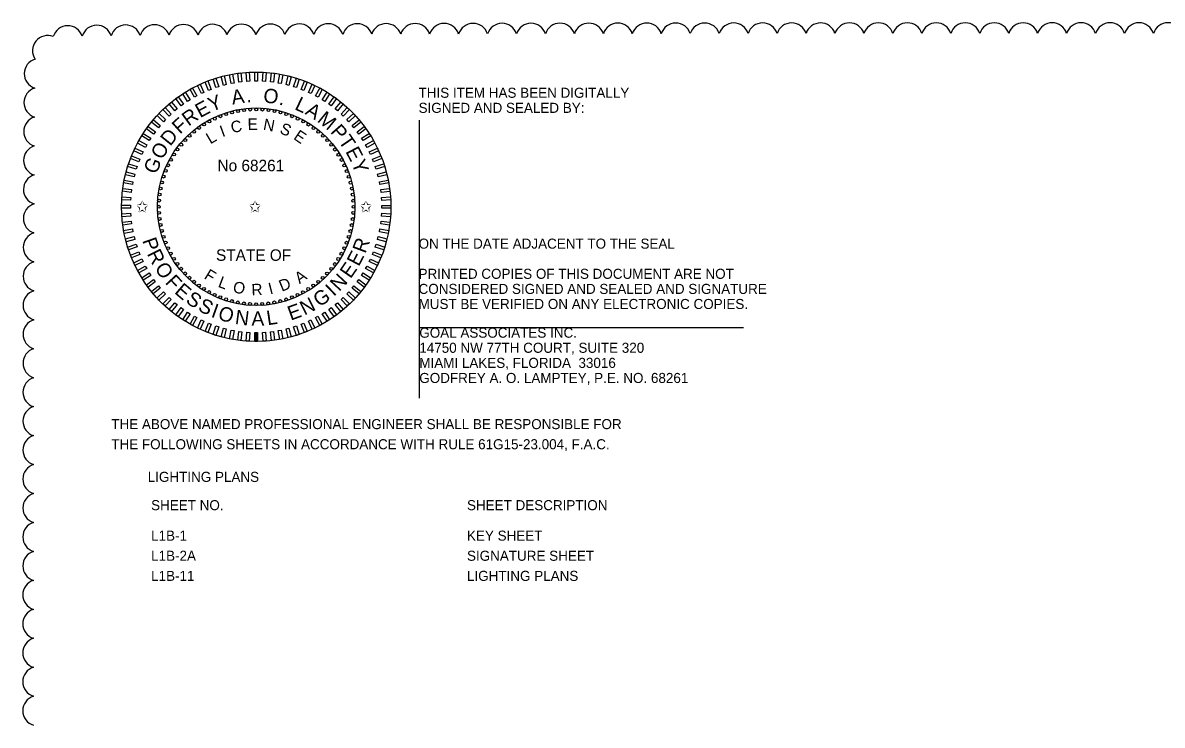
# Model space of a CAD drawing. Extents: x -811.2 to -767.6, y -2295.2 to -2235.1.
# Drawn here: x -811.11 to -803.18, y -2252.32 to -2247.44 of the extents above; entities that cross this region are included whole.
import ezdxf

# ---------------------------------------------------------------- set-up
doc = ezdxf.new("R2010")
doc.units = 0
for name, color, linetype in [('AdhocPoint_dp', 7, 'Continuous'), ('Cloud_dp', 7, 'Continuous'), ('PlotBorder_dp', 7, 'Continuous'), ('TextMinor', 7, 'Continuous'), ('TextMisc', 7, 'Continuous'), ('TextShtNo', 7, 'Continuous')]:
    doc.layers.add(name, color=color, linetype=linetype)

msp = doc.modelspace()

# ---------------------------------------------------------------- linework, layer by layer
at = {"layer": 'AdhocPoint_dp'}
for p, q in [((-808.3546, -2248.1122), (-808.3546, -2250.0469)), ((-808.3546, -2249.5569), (-806.0979, -2249.5569))]:
    msp.add_line(p, q, dxfattribs=at)
at = {"layer": 'Cloud_dp'}
for centre, start, end in [((-810.8012, -2247.5613), 18.59454, 163.59454), ((-810.5999, -2247.5581), 18.21421, 163.21421), ((-810.3985, -2247.5559), 18.04696, 163.04696), ((-810.197, -2247.5542), 17.94666, 162.94666), ((-809.9955, -2247.5527), 17.87787, 162.87787), ((-809.794, -2247.5515), 17.82689, 162.82689), ((-809.5924, -2247.5504), 17.78716, 162.78716), ((-809.3909, -2247.5495), 17.75505, 162.75505), ((-809.1894, -2247.5486), 17.72841, 162.72841), ((-808.9878, -2247.5478), 17.70584, 162.70584), ((-808.7863, -2247.5471), 17.6864, 162.6864), ((-808.5848, -2247.5465), 17.66942, 162.66942), ((-808.3832, -2247.546), 17.65443, 162.65443), ((-808.1817, -2247.5454), 17.64106, 162.64106), ((-807.9801, -2247.545), 17.62905, 162.62905), ((-807.7786, -2247.5445), 17.61817, 162.61817), ((-807.577, -2247.5441), 17.60826, 162.60826), ((-807.3755, -2247.5438), 17.59919, 162.59919), ((-807.174, -2247.5434), 17.59084, 162.59084), ((-806.9724, -2247.5431), 17.58312, 162.58312), ((-806.7709, -2247.5428), 17.57595, 162.57595), ((-806.5693, -2247.5426), 17.56928, 162.56928), ((-806.3678, -2247.5424), 17.56305, 162.56305), ((-806.1662, -2247.5421), 17.55721, 162.55721), ((-805.9647, -2247.5419), 17.55172, 162.55172), ((-805.7631, -2247.5418), 17.54655, 162.54655), ((-805.5616, -2247.5416), 17.54167, 162.54167), ((-805.3601, -2247.5415), 17.53705, 162.53705), ((-805.1585, -2247.5414), 17.53267, 162.53267), ((-804.957, -2247.5413), 17.52851, 162.52851), ((-804.7554, -2247.5412), 17.52455, 162.52455), ((-804.5539, -2247.5411), 17.52079, 162.52079), ((-804.3523, -2247.541), 17.51719, 162.51719), ((-804.1508, -2247.541), 17.51375, 162.51375), ((-803.9492, -2247.5409), 17.51046, 162.51046), ((-803.7477, -2247.5409), 17.50731, 162.50731), ((-803.5461, -2247.5409), 17.50428, 162.50428), ((-803.3446, -2247.5409), 17.50138, 162.50138), ((-803.143, -2247.5409), 17.5, 162.5), ((-810.9414, -2247.6297), 68.43954, 213.43954), ((-810.999, -2247.7891), 106.80445, 251.80445), ((-811.001, -2247.9905), 107.04367, 252.04367), ((-811.0025, -2248.192), 107.15618, 252.15618), ((-811.0035, -2248.3935), 107.22533, 252.22533), ((-811.0044, -2248.595), 107.27338, 252.27338), ((-811.0052, -2248.7966), 107.30928, 252.30928), ((-811.0058, -2248.9981), 107.33743, 252.33743), ((-811.0063, -2249.1996), 107.36027, 252.36027), ((-811.0068, -2249.4012), 107.37928, 252.37928), ((-811.0072, -2249.6027), 107.39543, 252.39543), ((-811.0075, -2249.8042), 107.40937, 252.40937), ((-811.0078, -2250.0058), 107.42156, 252.42156), ((-811.0081, -2250.2073), 107.43234, 252.43234), ((-811.0083, -2250.4089), 107.44197, 252.44197), ((-811.0085, -2250.6104), 107.45063, 252.45063), ((-811.0086, -2250.812), 107.45847, 252.45847), ((-811.0088, -2251.0135), 107.46563, 252.46563), ((-811.0089, -2251.2151), 107.47218, 252.47218), ((-811.009, -2251.4166), 107.47822, 252.47822), ((-811.009, -2251.6181), 107.4838, 252.4838), ((-811.0091, -2251.8197), 107.48899, 252.48899), ((-811.0091, -2252.0212), 107.49382, 252.49382), ((-811.0091, -2252.2228), 107.49843, 252.49843)]:
    msp.add_arc(centre, 0.1057, start, end, dxfattribs=at)
at = {"layer": 'TextMinor'}
for radius in [0.9375, 0.6875]:
    msp.add_circle((-809.4901, -2248.7156), radius, dxfattribs=at)
at = {"layer": 'TextShtNo'}
for p, q in [((-809.5001, -2249.6532), (-809.5003, -2249.5907)), ((-809.4901, -2249.6531), (-809.4903, -2249.5906)), ((-809.4801, -2249.6531), (-809.4803, -2249.5906))]:
    msp.add_line(p, q, dxfattribs=at)
for points in [[(-809.5897, -2247.8462), (-809.6097, -2247.8488), (-809.6175, -2247.7868), (-809.5975, -2247.7843)], [(-809.5349, -2247.8417), (-809.555, -2247.843), (-809.559, -2247.7806), (-809.5388, -2247.7794)], [(-809.4799, -2247.8406), (-809.5001, -2247.8406), (-809.5001, -2247.7782), (-809.4799, -2247.7782)], [(-809.425, -2247.843), (-809.4452, -2247.8417), (-809.4412, -2247.7794), (-809.4211, -2247.7807)], [(-809.3703, -2247.8488), (-809.3904, -2247.8463), (-809.3825, -2247.7843), (-809.3625, -2247.7868)], [(-809.8535, -2247.9195), (-809.8717, -2247.9281), (-809.8983, -2247.8716), (-809.8801, -2247.863)], [(-809.8028, -2247.8983), (-809.8215, -2247.9057), (-809.8445, -2247.8477), (-809.8258, -2247.8402)], [(-809.7508, -2247.8803), (-809.77, -2247.8865), (-809.7893, -2247.8271), (-809.7701, -2247.8209)], [(-809.6979, -2247.8656), (-809.7174, -2247.8706), (-809.7329, -2247.8101), (-809.7134, -2247.8051)], [(-809.6441, -2247.8542), (-809.6639, -2247.858), (-809.6756, -2247.7966), (-809.6558, -2247.7929)], [(-809.3162, -2247.858), (-809.336, -2247.8542), (-809.3243, -2247.7929), (-809.3045, -2247.7967)], [(-809.2626, -2247.8706), (-809.2822, -2247.8656), (-809.2667, -2247.8051), (-809.2471, -2247.8102)], [(-809.21, -2247.8866), (-809.2292, -2247.8803), (-809.2099, -2247.821), (-809.1907, -2247.8272)], [(-809.1585, -2247.9058), (-809.1773, -2247.8984), (-809.1543, -2247.8403), (-809.1355, -2247.8477)], [(-809.1083, -2247.9282), (-809.1266, -2247.9196), (-809.1, -2247.8631), (-809.0817, -2247.8717)], [(-809.9504, -2247.9714), (-809.9674, -2247.9822), (-810.0009, -2247.9295), (-809.9838, -2247.9186)], [(-809.9027, -2247.9439), (-809.9204, -2247.9537), (-809.9505, -2247.8989), (-809.9328, -2247.8892)], [(-809.0596, -2247.9537), (-809.0773, -2247.944), (-809.0473, -2247.8893), (-809.0296, -2247.899)], [(-809.0127, -2247.9823), (-809.0297, -2247.9715), (-808.9962, -2247.9187), (-808.9792, -2247.9296)], [(-810.0817, -2248.0708), (-810.0964, -2248.0846), (-810.1392, -2248.0391), (-810.1244, -2248.0253)], [(-810.04, -2248.0349), (-810.0556, -2248.0478), (-810.0954, -2247.9997), (-810.0798, -2247.9868)], [(-809.9962, -2248.0017), (-810.0125, -2248.0136), (-810.0492, -2247.9631), (-810.0329, -2247.9512)], [(-808.9676, -2248.0137), (-808.9839, -2248.0018), (-808.9472, -2247.9513), (-808.9308, -2247.9632)], [(-808.9245, -2248.0479), (-808.9401, -2248.035), (-808.9003, -2247.9869), (-808.8847, -2247.9998)], [(-808.8837, -2248.0847), (-808.8984, -2248.0709), (-808.8557, -2248.0254), (-808.841, -2248.0392)], [(-810.121, -2248.1092), (-810.1348, -2248.1239), (-810.1804, -2248.0812), (-810.1665, -2248.0665)], [(-808.8453, -2248.1241), (-808.8591, -2248.1093), (-808.8136, -2248.0666), (-808.7998, -2248.0813)], [(-810.192, -2248.1931), (-810.2039, -2248.2094), (-810.2544, -2248.1727), (-810.2426, -2248.1564)], [(-810.1579, -2248.15), (-810.1707, -2248.1656), (-810.2188, -2248.1258), (-810.206, -2248.1102)], [(-808.8094, -2248.1657), (-808.8223, -2248.1502), (-808.7742, -2248.1104), (-808.7613, -2248.1259)], [(-808.7762, -2248.2095), (-808.7881, -2248.1932), (-808.7376, -2248.1565), (-808.7257, -2248.1728)], [(-810.252, -2248.2852), (-810.2617, -2248.3028), (-810.3164, -2248.2728), (-810.3067, -2248.2551)], [(-810.2235, -2248.2382), (-810.2343, -2248.2552), (-810.287, -2248.2218), (-810.2762, -2248.2047)], [(-808.7459, -2248.2554), (-808.7567, -2248.2383), (-808.7039, -2248.2049), (-808.6931, -2248.2219)], [(-808.7184, -2248.303), (-808.7281, -2248.2853), (-808.6734, -2248.2552), (-808.6637, -2248.2729)], [(-810.2775, -2248.3338), (-810.2861, -2248.3521), (-810.3426, -2248.3255), (-810.334, -2248.3073)], [(-808.694, -2248.3523), (-808.7026, -2248.334), (-808.6461, -2248.3074), (-808.6375, -2248.3257)], [(-810.3192, -2248.4355), (-810.3254, -2248.4547), (-810.3848, -2248.4355), (-810.3786, -2248.4163)], [(-810.3, -2248.384), (-810.3074, -2248.4028), (-810.3654, -2248.3798), (-810.358, -2248.3611)], [(-808.6728, -2248.403), (-808.6802, -2248.3842), (-808.6222, -2248.3612), (-808.6147, -2248.38)], [(-808.6548, -2248.4549), (-808.661, -2248.4357), (-808.6016, -2248.4164), (-808.5954, -2248.4356)], [(-810.3351, -2248.4882), (-810.3401, -2248.5077), (-810.4006, -2248.4922), (-810.3956, -2248.4726)], [(-808.64, -2248.5079), (-808.6451, -2248.4883), (-808.5846, -2248.4728), (-808.5796, -2248.4924)], [(-810.3477, -2248.5417), (-810.3515, -2248.5615), (-810.4129, -2248.5498), (-810.4091, -2248.53)], [(-808.6287, -2248.5617), (-808.6325, -2248.5418), (-808.5711, -2248.5301), (-808.5673, -2248.55)], [(-810.3628, -2248.6505), (-810.3641, -2248.6707), (-810.4264, -2248.6668), (-810.4251, -2248.6466)], [(-810.357, -2248.5959), (-810.3595, -2248.6159), (-810.4215, -2248.6081), (-810.4189, -2248.588)], [(-808.6207, -2248.6161), (-808.6232, -2248.596), (-808.5613, -2248.5882), (-808.5588, -2248.6082)], [(-808.6162, -2248.6709), (-808.6174, -2248.6507), (-808.5551, -2248.6468), (-808.5539, -2248.6669)], [(-810.3652, -2248.7054), (-810.3652, -2248.7256), (-810.4276, -2248.7256), (-810.4276, -2248.7054)], [(-808.6151, -2248.7258), (-808.6151, -2248.7056), (-808.5527, -2248.7056), (-808.5527, -2248.7258)], [(-810.3641, -2248.7604), (-810.3628, -2248.7806), (-810.4251, -2248.7845), (-810.4264, -2248.7643)], [(-810.3595, -2248.8152), (-810.357, -2248.8352), (-810.4189, -2248.8431), (-810.4215, -2248.823)], [(-808.6233, -2248.8354), (-808.6207, -2248.8154), (-808.5588, -2248.8232), (-808.5613, -2248.8432)], [(-808.6175, -2248.7807), (-808.6162, -2248.7606), (-808.5539, -2248.7645), (-808.5551, -2248.7847)], [(-810.3516, -2248.8696), (-810.3478, -2248.8894), (-810.4091, -2248.9011), (-810.4129, -2248.8813)], [(-808.6325, -2248.8896), (-808.6287, -2248.8698), (-808.5674, -2248.8815), (-808.5712, -2248.9013)], [(-810.3402, -2248.9234), (-810.3352, -2248.9429), (-810.3957, -2248.9585), (-810.4007, -2248.9389)], [(-810.3255, -2248.9763), (-810.3192, -2248.9955), (-810.3786, -2249.0148), (-810.3849, -2248.9956)], [(-808.6611, -2248.9957), (-808.6548, -2248.9765), (-808.5954, -2248.9958), (-808.6017, -2249.015)], [(-808.6451, -2248.9431), (-808.6401, -2248.9236), (-808.5796, -2248.9391), (-808.5846, -2248.9586)], [(-810.3075, -2249.0283), (-810.3, -2249.0471), (-810.3581, -2249.07), (-810.3655, -2249.0513)], [(-808.6803, -2249.0472), (-808.6729, -2249.0285), (-808.6148, -2249.0514), (-808.6222, -2249.0702)], [(-810.2862, -2249.079), (-810.2776, -2249.0973), (-810.3341, -2249.1238), (-810.3427, -2249.1056)], [(-810.2618, -2249.1283), (-810.2521, -2249.1459), (-810.3068, -2249.176), (-810.3165, -2249.1583)], [(-808.7282, -2249.1461), (-808.7185, -2249.1284), (-808.6638, -2249.1585), (-808.6735, -2249.1762)], [(-808.7027, -2249.0974), (-808.6941, -2249.0792), (-808.6376, -2249.1057), (-808.6462, -2249.124)], [(-810.2344, -2249.1759), (-810.2236, -2249.1929), (-810.2763, -2249.2264), (-810.2871, -2249.2094)], [(-808.7568, -2249.1931), (-808.746, -2249.1761), (-808.6932, -2249.2095), (-808.704, -2249.2266)], [(-810.204, -2249.2217), (-810.1922, -2249.2381), (-810.2427, -2249.2748), (-810.2545, -2249.2584)], [(-810.1708, -2249.2656), (-810.158, -2249.2811), (-810.2061, -2249.3209), (-810.2189, -2249.3054)], [(-808.8224, -2249.2812), (-808.8095, -2249.2657), (-808.7614, -2249.3055), (-808.7743, -2249.321)], [(-808.7882, -2249.2382), (-808.7763, -2249.2219), (-808.7258, -2249.2586), (-808.7377, -2249.2749)], [(-810.135, -2249.3072), (-810.1211, -2249.3219), (-810.1667, -2249.3647), (-810.1805, -2249.35)], [(-810.0965, -2249.3465), (-810.0818, -2249.3603), (-810.1246, -2249.4059), (-810.1393, -2249.392)], [(-808.8985, -2249.3605), (-808.8838, -2249.3467), (-808.8411, -2249.3922), (-808.8558, -2249.406)], [(-808.8592, -2249.3221), (-808.8454, -2249.3073), (-808.7999, -2249.3501), (-808.8137, -2249.3648)], [(-810.0557, -2249.3834), (-810.0402, -2249.3962), (-810.08, -2249.4443), (-810.0955, -2249.4315)], [(-810.0127, -2249.4176), (-809.9964, -2249.4294), (-810.0331, -2249.4799), (-810.0494, -2249.4681)], [(-809.9676, -2249.449), (-809.9505, -2249.4598), (-809.984, -2249.5125), (-810.001, -2249.5017)], [(-809.0299, -2249.4599), (-809.0128, -2249.4491), (-808.9794, -2249.5018), (-808.9964, -2249.5126)], [(-808.984, -2249.4295), (-808.9677, -2249.4177), (-808.931, -2249.4682), (-808.9473, -2249.4801)], [(-808.9402, -2249.3964), (-808.9247, -2249.3835), (-808.8848, -2249.4316), (-808.9004, -2249.4445)], [(-809.9206, -2249.4775), (-809.9029, -2249.4872), (-809.933, -2249.542), (-809.9507, -2249.5322)], [(-809.8719, -2249.503), (-809.8536, -2249.5116), (-809.8802, -2249.5681), (-809.8985, -2249.5595)], [(-809.8217, -2249.5255), (-809.8029, -2249.5329), (-809.8259, -2249.591), (-809.8447, -2249.5835)], [(-809.1775, -2249.533), (-809.1587, -2249.5255), (-809.1357, -2249.5836), (-809.1545, -2249.591)], [(-809.1268, -2249.5117), (-809.1085, -2249.5031), (-809.0819, -2249.5596), (-809.1002, -2249.5682)], [(-809.0775, -2249.4873), (-809.0598, -2249.4776), (-809.0297, -2249.5323), (-809.0474, -2249.5421)], [(-809.7702, -2249.5447), (-809.751, -2249.5509), (-809.7703, -2249.6103), (-809.7895, -2249.6041)], [(-809.7176, -2249.5606), (-809.698, -2249.5657), (-809.7136, -2249.6261), (-809.7331, -2249.6211)], [(-809.6641, -2249.5733), (-809.6443, -2249.577), (-809.656, -2249.6384), (-809.6758, -2249.6346)], [(-809.6099, -2249.5825), (-809.5899, -2249.585), (-809.5977, -2249.647), (-809.6177, -2249.6444)], [(-809.5552, -2249.5883), (-809.5351, -2249.5896), (-809.539, -2249.6519), (-809.5592, -2249.6506)], [(-809.5003, -2249.5907), (-809.4801, -2249.5907), (-809.4801, -2249.6531), (-809.5003, -2249.6531)], [(-809.4453, -2249.5896), (-809.4252, -2249.5883), (-809.4213, -2249.6506), (-809.4414, -2249.6519)], [(-809.3906, -2249.585), (-809.3705, -2249.5825), (-809.3627, -2249.6445), (-809.3827, -2249.647)], [(-809.3362, -2249.5771), (-809.3163, -2249.5733), (-809.3046, -2249.6346), (-809.3245, -2249.6384)], [(-809.2824, -2249.5657), (-809.2628, -2249.5607), (-809.2473, -2249.6212), (-809.2668, -2249.6262)], [(-809.2294, -2249.551), (-809.2102, -2249.5447), (-809.1909, -2249.6041), (-809.2101, -2249.6104)]]:
    msp.add_lwpolyline(points, close=True, dxfattribs=at)
for centre in [(-809.7781, -2248.1024), (-809.739, -2248.0855), (-809.6989, -2248.0712), (-809.6581, -2248.0593), (-809.6165, -2248.0501), (-809.5745, -2248.0434), (-809.5321, -2248.0395), (-809.4896, -2248.0382), (-809.447, -2248.0395), (-809.4047, -2248.0436), (-809.3626, -2248.0503), (-809.3211, -2248.0596), (-809.2802, -2248.0715), (-809.2402, -2248.0859), (-809.2012, -2248.1029), (-809.9215, -2248.1933), (-809.8879, -2248.1672), (-809.8527, -2248.1433), (-809.816, -2248.1217), (-809.1633, -2248.1222), (-809.1266, -2248.1439), (-809.0915, -2248.1679), (-809.0579, -2248.194), (-809.9836, -2248.2515), (-809.9535, -2248.2214), (-809.026, -2248.2222), (-808.9959, -2248.2523), (-810.0618, -2248.3522), (-810.0379, -2248.317), (-810.0118, -2248.2834), (-808.9678, -2248.2842), (-808.9417, -2248.3179), (-808.9178, -2248.3531), (-810.1029, -2248.4267), (-810.0835, -2248.3888), (-808.8962, -2248.3898), (-808.8769, -2248.4277), (-810.1343, -2248.5057), (-810.1198, -2248.4657), (-808.86, -2248.4668), (-808.8456, -2248.5068), (-810.1555, -2248.5881), (-810.1462, -2248.5466), (-808.8338, -2248.5477), (-808.8245, -2248.5892), (-810.1622, -2248.6302), (-808.8179, -2248.6313), (-810.1676, -2248.7151), (-810.1662, -2248.6725), (-808.814, -2248.6737), (-808.8127, -2248.7162), (-810.1663, -2248.7576), (-810.1623, -2248.8), (-808.8181, -2248.8011), (-808.814, -2248.7587), (-810.1557, -2248.842), (-810.1464, -2248.8836), (-808.8341, -2248.8847), (-808.8248, -2248.8431), (-810.1346, -2248.9244), (-810.1202, -2248.9645), (-808.8604, -2248.9656), (-808.846, -2248.9255), (-810.1034, -2249.0036), (-810.0841, -2249.0415), (-808.8967, -2249.0425), (-808.8774, -2249.0046), (-810.0624, -2249.0782), (-810.0385, -2249.1134), (-808.9424, -2249.1143), (-808.9184, -2249.0791), (-810.0125, -2249.147), (-809.9844, -2249.179), (-809.9543, -2249.2091), (-809.0268, -2249.2099), (-808.9967, -2249.1798), (-808.9685, -2249.1479), (-809.9224, -2249.2373), (-809.8888, -2249.2634), (-809.8536, -2249.2873), (-809.1276, -2249.2879), (-809.0924, -2249.264), (-809.0587, -2249.238), (-809.817, -2249.309), (-809.7791, -2249.3284), (-809.74, -2249.3453), (-809.7, -2249.3598), (-809.6591, -2249.3717), (-809.6176, -2249.381), (-809.3637, -2249.3812), (-809.3222, -2249.372), (-809.2813, -2249.3601), (-809.2413, -2249.3457), (-809.2022, -2249.3289), (-809.1642, -2249.3096), (-809.5756, -2249.3877), (-809.5332, -2249.3917), (-809.4901, -2249.3931), (-809.4481, -2249.3918), (-809.4058, -2249.3878)]:
    msp.add_circle(centre, 0.01, dxfattribs=at)

# ---------------------------------------------------------------- texts
at = {"layer": 'PlotBorder_dp'}
for s, p in [('THIS ITEM HAS BEEN DIGITALLY', (-808.3596, -2247.9571)), ('SIGNED AND SEALED BY:', (-808.3596, -2248.0621)), ('ON THE DATE ADJACENT TO THE SEAL', (-808.3596, -2249.0071)), ('PRINTED COPIES OF THIS DOCUMENT ARE NOT ', (-808.3596, -2249.2171)), ('CONSIDERED SIGNED AND SEALED AND SIGNATURE ', (-808.3596, -2249.3221)), ('MUST BE VERIFIED ON ANY ELECTRONIC COPIES.', (-808.3596, -2249.4271)), ('GOAL ASSOCIATES INC.', (-808.3546, -2249.6269)), ('14750 NW 77TH COURT, SUITE 320', (-808.3546, -2249.7319)), ('MIAMI LAKES, FLORIDA  33016', (-808.3546, -2249.8369)), ('GODFREY A. O. LAMPTEY, P.E. NO. 68261', (-808.3546, -2249.9419)), ('THE ABOVE NAMED PROFESSIONAL ENGINEER SHALL BE RESPONSIBLE FOR ', (-810.4987, -2250.2631)), ('THE FOLLOWING SHEETS IN ACCORDANCE WITH RULE 61G15-23.004, F.A.C.', (-810.4987, -2250.4031)), ('LIGHTING PLANS', (-810.245, -2250.6301))]:
    msp.add_text(s, height=0.07, dxfattribs=at).set_placement(p)
at = {"layer": 'TextMisc'}
for s, p in [('SHEET NO.', (-810.2215, -2250.8271)), ('SHEET DESCRIPTION', (-808.0226, -2250.8271)), ('L1B-1', (-810.2215, -2251.0393)), ('KEY SHEET', (-808.0226, -2251.0393)), ('L1B-2A', (-810.2215, -2251.1793)), ('SIGNATURE SHEET', (-808.0226, -2251.1793)), ('L1B-11', (-810.2215, -2251.3193)), ('LIGHTING PLANS', (-808.0226, -2251.3193))]:
    msp.add_text(s, height=0.07, dxfattribs=at).set_placement(p)
at = {"layer": 'TextShtNo'}
for s, height, rotation, p in [('Y', 0.1, 21.06329, (-809.8021, -2248.0562)), ('A', 0.1, 8.80884, (-809.6551, -2248.005)), ('O', 0.1, 352.18771, (-809.4449, -2247.9875)), ('E', 0.1, 28.10553, (-809.8806, -2248.0994)), ('.', 0.1, 1.04184, (-809.5575, -2247.9892)), ('.', 0.1, 343.52684, (-809.3358, -2248.0026)), ('L', 0.1, 334.67271, (-809.2279, -2248.0349)), ('A', 0.1, 328.40959, (-809.1552, -2248.0676)), ('F', 0.1, 42.37723, (-810.0205, -2248.2147)), ('R', 0.1, 35.92688, (-809.9609, -2248.1583)), ('E', 0.08, 0.41861, (-809.5498, -2248.1806)), ('N', 0.08, 349.29143, (-809.4455, -2248.1791)), ('M', 0.1, 320.6426, (-809.0707, -2248.1188)), ('D', 0.1, 50.8569, (-810.0886, -2248.2984)), ('I', 0.08, 20.01168, (-809.7258, -2248.2316)), ('C', 0.08, 12.20255, (-809.6579, -2248.204)), ('S', 0.08, 337.02207, (-809.3325, -2248.2008)), ('E', 0.08, 325.86633, (-809.2358, -2248.2411)), ('P', 0.1, 311.19658, (-808.9784, -2248.1957)), ('L', 0.08, 30.40215, (-809.8093, -2248.282)), ('T', 0.1, 304.45632, (-808.9209, -2248.2594)), ('O', 0.1, 59.51777, (-810.1446, -2248.3933)), ('E', 0.1, 297.63152, (-808.8707, -2248.3302)), ('G', 0.1, 68.0518, (-810.1851, -2248.494)), ('Y', 0.1, 290.58928, (-808.8281, -2248.4091)), ('P', 0.1, 289.40551, (-810.2848, -2248.9502)), ('R', 0.1, 69.5134, (-808.7299, -2249.0453)), ('R', 0.1, 296.14576, (-810.2518, -2249.0419)), ('E', 0.1, 62.47116, (-808.7761, -2249.136)), ('O', 0.1, 303.96711, (-810.2003, -2249.1425)), ('E', 0.1, 55.42892, (-808.833, -2249.2204)), ('F', 0.1, 312.62798, (-810.1279, -2249.2446)), ('F', 0.08, 328.72408, (-809.8582, -2249.2122)), ('L', 0.08, 339.29159, (-809.7609, -2249.2713)), ('D', 0.08, 22.01279, (-809.312, -2249.3075)), ('A', 0.08, 34.49917, (-809.1883, -2249.255)), ('N', 0.1, 47.17876, (-808.9123, -2249.3095)), ('E', 0.1, 319.07833, (-810.0645, -2249.3129)), ('O', 0.08, 349.68206, (-809.6562, -2249.311)), ('R', 0.08, 2.33977, (-809.5217, -2249.3329)), ('I', 0.08, 14.20366, (-809.3941, -2249.3262)), ('G', 0.1, 35.11153, (-809.0492, -2249.4172)), ('I', 0.1, 43.64556, (-808.9499, -2249.344)), ('S', 0.1, 326.12056, (-809.9869, -2249.3788)), ('S', 0.1, 333.193, (-809.9015, -2249.4349)), ('N', 0.1, 26.86136, (-809.1544, -2249.4732)), ('I', 0.1, 340.26543, (-809.8098, -2249.4801)), ('O', 0.1, 343.79863, (-809.7621, -2249.4983)), ('N', 0.1, 352.45949, (-809.6411, -2249.5304)), ('A', 0.1, 0.70966, (-809.5227, -2249.5436)), ('L', 0.1, 8.47665, (-809.4105, -2249.5404)), ('E', 0.1, 19.81912, (-809.2498, -2249.5086))]:
    msp.add_text(s, height=height, rotation=rotation, dxfattribs=at).set_placement(p)
for s, p in [('No 68261', (-809.7591, -2248.4684)), ('✩', (-810.3251, -2248.7536)), ('✩', (-809.5404, -2248.7536)), ('✩', (-808.7685, -2248.7536)), ('STATE OF', (-809.7698, -2249.0918))]:
    msp.add_text(s, height=0.08, dxfattribs=at).set_placement(p)

doc.saveas('drawing.dxf')
